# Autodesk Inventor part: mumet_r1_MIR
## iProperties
Shininess: 64.0
Length Units: 11272
Angle Units: 11279
Time Units: 11290
Mass Units: 11286
Length Display Precision: 3
Angle Display Precision: 2
Compacted: True
Part Number: mumet_r1_MIR
Document SubType Name: Modeling
Created: 2004-08
Designer: John Blackburn
Material: Default
Manufacturer: Standard
Standards Organization: Custom
Density: 0.0
Volumn: 0.0
Area: 0.0
PropertySet Name: Model Information
Control State: 0
Master: False
Checked Out: False
Author: John Blackburn
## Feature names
1. Derived Body1 [Tagging]
